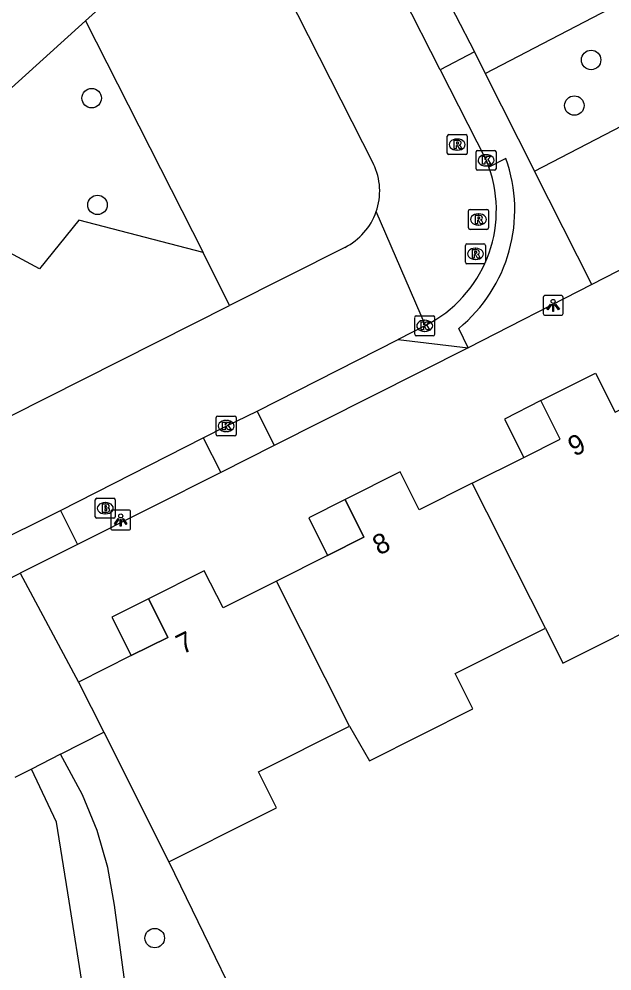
# Model space of a CAD drawing. Extents: x 162722 to 165099, y 384721 to 386283.
# Drawn here: x 163730.52 to 163760.3, y 385039.4 to 385087.19 of the extents above; entities that cross this region are included whole.
import ezdxf

# ---------------------------------------------------------------- set-up
doc = ezdxf.new("R2010")
doc.units = 0
for name, color, linetype in [('IMGEO_Boom', 7, 'Continuous'), ('IMGEO_Brandkraan', 7, 'Continuous'), ('IMGEO_Groenvoorziening', 7, 'Continuous'), ('IMGEO_Kolk', 7, 'Continuous'), ('IMGEO_Lichtpunt', 7, 'Continuous'), ('IMGEO_Pand', 7, 'Continuous'), ('IMGEO_Pand_nummerreeks', 7, 'Continuous'), ('IMGEO_Pand_overbouw', 7, 'Continuous'), ('IMGEO_Parkeervlak_open', 7, 'Continuous'), ('IMGEO_Rijbaan_lokaal_open', 7, 'Continuous'), ('IMGEO_Rioolput', 7, 'Continuous'), ('IMGEO_Voetpad_open', 7, 'Continuous')]:
    doc.layers.add(name, color=color, linetype=linetype)

msp = doc.modelspace()

# ---------------------------------------------------------------- linework, layer by layer
at = {"layer": 'IMGEO_Boom'}
for centre in [(163759.25, 385085.133), (163734.168, 385083.216), (163758.406, 385082.843), (163734.462, 385077.855), (163737.335, 385041.047)]:
    msp.add_circle(centre, 0.489, dxfattribs=at)
at = {"layer": 'IMGEO_Brandkraan'}
for p, q in [((163734.352, 385062.203), (163734.352, 385063.055)), ((163734.427, 385063.129), (163735.279, 385063.129)), ((163735.353, 385063.055), (163735.353, 385062.203)), ((163734.84, 385062.909), (163734.865, 385062.909)), ((163735.279, 385062.129), (163734.427, 385062.129)), ((163734.863, 385062.349), (163734.838, 385062.349))]:
    msp.add_line(p, q, dxfattribs=at)
for points in [[(163734.352, 385062.203), (163734.352, 385063.055)], [(163734.427, 385063.129), (163735.279, 385063.129)], [(163735.353, 385063.055), (163735.353, 385062.203)], [(163734.7, 385062.829), (163734.7, 385062.429), (163734.913, 385062.429)], [(163734.931, 385062.829), (163734.7, 385062.829)], [(163734.879, 385062.748), (163734.825, 385062.748), (163734.825, 385062.672)], [(163734.825, 385062.672), (163734.878, 385062.672)], [(163734.887, 385062.596), (163734.825, 385062.596), (163734.825, 385062.515)], [(163735.279, 385062.129), (163734.427, 385062.129)], [(163734.825, 385062.515), (163734.887, 385062.515)]]:
    msp.add_lwpolyline(points, dxfattribs=at)
for centre, radius, start, end in [((163734.429, 385063.053), 0.0765, 91.552, 178.448), ((163734.429, 385063.053), 0.0765, 91.552, 178.448), ((163735.277, 385063.053), 0.0765, 1.552, 88.448), ((163735.277, 385063.053), 0.0765, 1.552, 88.448), ((163734.88, 385062.71), 0.0379, 267.8285, 90.9355), ((163734.888, 385062.555), 0.0404, 269.8759, 90.5077), ((163734.935, 385062.684), 0.145, 59.4692, 91.5367), ((163734.96, 385062.731), 0.0922, 285.5137, 58.1501), ((163734.965, 385062.539), 0.105, 301.3115, 78.989), ((163734.429, 385062.205), 0.0765, 181.552, 268.448), ((163734.429, 385062.205), 0.0765, 181.552, 268.448), ((163734.919, 385062.68), 0.251, 268.6676, 293.5347), ((163735.277, 385062.205), 0.0765, 271.552, 358.448), ((163735.277, 385062.205), 0.0765, 271.552, 358.448)]:
    msp.add_arc(centre, radius, start, end, dxfattribs=at)
for centre, major_axis, ratio, start_param, end_param in [((163734.839, 385062.629), (-0.387, 0.002), 0.722429, 4.712389, 7.853982), ((163734.864, 385062.629), (-0.39, 0.002), 0.717154, 1.570796, 4.712389)]:
    msp.add_ellipse(centre, major_axis=major_axis, ratio=ratio, start_param=start_param, end_param=end_param, dxfattribs=at)
at = {"layer": 'IMGEO_Groenvoorziening'}
for points in [[(163753.931, 385084.458), (163761.818, 385088.577), (163781.027, 385098.268), (163760.145, 385139.341), (163746.528, 385166.095)], [(163733.852, 385087.089), (163739.773, 385075.459)], [(163739.773, 385075.459), (163733.516, 385077.082), (163731.546, 385074.648), (163729.808, 385075.575), (163728.649, 385075.923), (163727.49, 385076.039), (163727.143, 385076.734), (163727.954, 385078.241), (163728.765, 385080.095), (163728.359, 385082.125)], [(163741.098, 385072.809), (163739.773, 385075.459)], [(163738.045, 385044.879), (163743.285, 385034.094)]]:
    msp.add_lwpolyline(points, dxfattribs=at)
at = {"layer": 'IMGEO_Kolk'}
for p, q in [((163753.473, 385079.668), (163753.473, 385080.52)), ((163753.548, 385080.594), (163754.4, 385080.594)), ((163753.961, 385080.374), (163753.986, 385080.374)), ((163754.474, 385080.52), (163754.474, 385079.668)), ((163753.984, 385079.814), (163753.959, 385079.814)), ((163754.4, 385079.594), (163753.548, 385079.594)), ((163750.392, 385071.359), (163750.392, 385072.211)), ((163750.467, 385072.285), (163751.319, 385072.285)), ((163751.393, 385072.211), (163751.393, 385071.359)), ((163750.88, 385072.065), (163750.905, 385072.065)), ((163751.319, 385071.285), (163750.467, 385071.285)), ((163750.903, 385071.505), (163750.878, 385071.505)), ((163740.422, 385066.329), (163740.422, 385067.181)), ((163740.497, 385067.255), (163741.349, 385067.255)), ((163740.91, 385067.035), (163740.935, 385067.035)), ((163741.423, 385067.181), (163741.423, 385066.329)), ((163740.933, 385066.475), (163740.908, 385066.475)), ((163741.349, 385066.255), (163740.497, 385066.255))]:
    msp.add_line(p, q, dxfattribs=at)
for points in [[(163753.473, 385079.668), (163753.473, 385080.52)], [(163753.548, 385080.594), (163754.4, 385080.594)], [(163753.794, 385080.294), (163753.917, 385080.294), (163753.917, 385080.143), (163754.047, 385080.294), (163754.211, 385080.294), (163754.065, 385080.143), (163754.218, 385079.894), (163754.066, 385079.894), (163753.981, 385080.058), (163753.917, 385079.991), (163753.917, 385079.894), (163753.794, 385079.894), (163753.794, 385080.294)], [(163754.474, 385080.52), (163754.474, 385079.668)], [(163754.4, 385079.594), (163753.548, 385079.594)], [(163750.392, 385071.359), (163750.392, 385072.211)], [(163750.467, 385072.285), (163751.319, 385072.285)], [(163751.393, 385072.211), (163751.393, 385071.359)], [(163750.713, 385071.985), (163750.836, 385071.985), (163750.836, 385071.834), (163750.966, 385071.985), (163751.13, 385071.985), (163750.984, 385071.834), (163751.137, 385071.585), (163750.985, 385071.585), (163750.9, 385071.749), (163750.836, 385071.682), (163750.836, 385071.585), (163750.713, 385071.585), (163750.713, 385071.985)], [(163751.319, 385071.285), (163750.467, 385071.285)], [(163740.422, 385066.329), (163740.422, 385067.181)], [(163740.497, 385067.255), (163741.349, 385067.255)], [(163740.743, 385066.955), (163740.866, 385066.955), (163740.866, 385066.804), (163740.996, 385066.955), (163741.16, 385066.955), (163741.014, 385066.804), (163741.167, 385066.555), (163741.015, 385066.555), (163740.93, 385066.719), (163740.866, 385066.652), (163740.866, 385066.555), (163740.743, 385066.555), (163740.743, 385066.955)], [(163741.423, 385067.181), (163741.423, 385066.329)], [(163741.349, 385066.255), (163740.497, 385066.255)]]:
    msp.add_lwpolyline(points, dxfattribs=at)
for centre, start, end in [((163753.55, 385080.518), 91.552, 178.448), ((163753.55, 385080.518), 91.552, 178.448), ((163754.398, 385080.518), 1.552, 88.448), ((163754.398, 385080.518), 1.552, 88.448), ((163753.55, 385079.67), 181.552, 268.448), ((163753.55, 385079.67), 181.552, 268.448), ((163754.398, 385079.67), 271.552, 358.448), ((163754.398, 385079.67), 271.552, 358.448), ((163750.469, 385072.209), 91.552, 178.448), ((163750.469, 385072.209), 91.552, 178.448), ((163751.317, 385072.209), 1.552, 88.448), ((163751.317, 385072.209), 1.552, 88.448), ((163750.469, 385071.361), 181.552, 268.448), ((163750.469, 385071.361), 181.552, 268.448), ((163751.317, 385071.361), 271.552, 358.448), ((163751.317, 385071.361), 271.552, 358.448), ((163740.499, 385067.179), 91.552, 178.448), ((163740.499, 385067.179), 91.552, 178.448), ((163741.347, 385067.179), 1.552, 88.448), ((163741.347, 385067.179), 1.552, 88.448), ((163740.499, 385066.331), 181.552, 268.448), ((163740.499, 385066.331), 181.552, 268.448), ((163741.347, 385066.331), 271.552, 358.448), ((163741.347, 385066.331), 271.552, 358.448)]:
    msp.add_arc(centre, 0.0765, start, end, dxfattribs=at)
for centre, major_axis, ratio, start_param, end_param in [((163753.96, 385080.094), (-0.387, 0.002), 0.722429, 4.712389, 7.853982), ((163753.985, 385080.094), (-0.39, 0.002), 0.717154, 1.570796, 4.712389), ((163750.879, 385071.785), (-0.387, 0.002), 0.722429, 4.712389, 7.853982), ((163750.904, 385071.785), (-0.39, 0.002), 0.717154, 1.570796, 4.712389), ((163740.909, 385066.755), (-0.387, 0.002), 0.722429, 4.712389, 7.853982), ((163740.934, 385066.755), (-0.39, 0.002), 0.717154, 1.570796, 4.712389)]:
    msp.add_ellipse(centre, major_axis=major_axis, ratio=ratio, start_param=start_param, end_param=end_param, dxfattribs=at)
at = {"layer": 'IMGEO_Lichtpunt'}
for p, q in [((163756.844, 385073.214), (163756.844, 385072.407)), ((163756.844, 385073.214), (163756.844, 385072.407)), ((163757.746, 385073.309), (163756.938, 385073.309)), ((163757.746, 385073.309), (163756.938, 385073.309)), ((163757.84, 385072.407), (163757.84, 385073.214)), ((163757.84, 385072.407), (163757.84, 385073.214)), ((163756.938, 385072.313), (163757.746, 385072.313)), ((163756.938, 385072.313), (163757.746, 385072.313)), ((163735.127, 385062.441), (163735.127, 385061.634)), ((163735.127, 385062.441), (163735.127, 385061.634)), ((163736.029, 385062.536), (163735.221, 385062.536)), ((163736.029, 385062.536), (163735.221, 385062.536)), ((163736.123, 385061.634), (163736.123, 385062.441)), ((163736.123, 385061.634), (163736.123, 385062.441)), ((163735.221, 385061.54), (163736.029, 385061.54)), ((163735.221, 385061.54), (163736.029, 385061.54))]:
    msp.add_line(p, q, dxfattribs=at)
for points in [[(163757.218, 385072.878), (163757.257, 385072.85), (163757.069, 385072.588), (163757.031, 385072.615), (163757.218, 385072.878)], [(163757.32, 385072.83), (163757.367, 385072.83), (163757.367, 385072.508), (163757.32, 385072.508), (163757.32, 385072.83)], [(163757.43, 385072.85), (163757.468, 385072.877), (163757.655, 385072.615), (163757.616, 385072.587), (163757.43, 385072.85)], [(163735.501, 385062.105), (163735.54, 385062.077), (163735.352, 385061.815), (163735.314, 385061.842), (163735.501, 385062.105)], [(163735.713, 385062.077), (163735.751, 385062.104), (163735.938, 385061.842), (163735.899, 385061.814), (163735.713, 385062.077)], [(163735.603, 385062.057), (163735.65, 385062.057), (163735.65, 385061.735), (163735.603, 385061.735), (163735.603, 385062.057)]]:
    msp.add_lwpolyline(points, dxfattribs=at)
for centre in [(163757.343, 385073.012), (163735.626, 385062.239)]:
    msp.add_circle(centre, 0.0994, dxfattribs=at)
for centre, start, end in [((163756.938, 385073.214), 90, 180), ((163756.938, 385073.214), 90, 180), ((163757.746, 385073.214), 0, 90), ((163757.746, 385073.214), 0, 90), ((163756.938, 385072.407), 180, 270), ((163756.938, 385072.407), 180, 270), ((163757.746, 385072.407), 270, 0), ((163757.746, 385072.407), 270, 360), ((163735.221, 385062.441), 90, 180), ((163735.221, 385062.441), 90, 180), ((163736.029, 385062.441), 0, 90), ((163736.029, 385062.441), 0, 90), ((163735.221, 385061.634), 180, 270), ((163735.221, 385061.634), 180, 270), ((163736.029, 385061.634), 270, 0), ((163736.029, 385061.634), 270, 360)]:
    msp.add_arc(centre, 0.0946, start, end, dxfattribs=at)
at = {"layer": 'IMGEO_Pand'}
for points in [[(163753.284, 385063.881), (163755.865, 385065.177), (163757.701, 385066.099), (163756.732, 385068.029), (163759.469, 385069.404), (163760.451, 385067.447), (163763.416, 385068.936)], [(163753.284, 385063.881), (163750.622, 385062.544), (163749.666, 385064.449), (163746.895, 385063.058), (163747.84, 385061.177), (163746.017, 385060.261), (163743.454, 385058.974)], [(163756.951, 385056.602), (163753.284, 385063.881)], [(163756.951, 385056.602), (163757.832, 385054.849), (163758.028, 385054.947), (163762.769, 385057.329), (163763.622, 385055.631), (163768.76, 385058.212), (163767.9, 385060.037)], [(163743.454, 385058.974), (163740.765, 385057.623), (163739.826, 385059.492), (163737.023, 385058.085), (163737.035, 385058.063), (163737.998, 385056.138), (163736.157, 385055.226), (163733.515, 385053.899)], [(163747.123, 385051.691), (163743.454, 385058.974)], [(163747.123, 385051.691), (163748.113, 385049.942), (163753.315, 385052.554), (163752.423, 385054.328), (163756.951, 385056.602)], [(163733.515, 385053.899), (163734.778, 385051.385)], [(163738.045, 385044.879), (163742.514, 385047.123), (163743.452, 385047.594), (163742.548, 385049.393), (163747.123, 385051.691)], [(163734.778, 385051.385), (163738.045, 385044.879)]]:
    msp.add_lwpolyline(points, dxfattribs=at)
at = {"layer": 'IMGEO_Pand_overbouw'}
for points in [[(163756.732, 385068.029), (163754.896, 385067.107), (163755.865, 385065.177), (163757.701, 385066.099)], [(163746.895, 385063.058), (163745.072, 385062.142), (163746.017, 385060.261), (163747.84, 385061.177)], [(163737.023, 385058.085), (163735.185, 385057.162), (163736.157, 385055.226), (163737.998, 385056.138)]]:
    msp.add_lwpolyline(points, close=True, dxfattribs=at)
at = {"layer": 'IMGEO_Parkeervlak_open'}
for points in [[(163730.584, 385059.363), (163733.515, 385053.899)], [(163732.602, 385050.277), (163734.778, 385051.385)], [(163731.143, 385049.533), (163730.314, 385049.111)]]:
    msp.add_lwpolyline(points, dxfattribs=at)
at = {"layer": 'IMGEO_Rijbaan_lokaal_open'}
for points in [[(163733.852, 385087.089), (163738.829, 385091.585)], [(163742.868, 385090.668), (163748.325, 385079.906)], [(163751.676, 385084.642), (163749.785, 385088.372)], [(163728.359, 385082.125), (163733.852, 385087.089)], [(163751.676, 385084.642), (163753.974, 385080.094), (163754.119, 385079.757)], [(163756.413, 385079.553), (163766.533, 385084.8)], [(163759.29, 385073.861), (163756.413, 385079.553)], [(163769.461, 385079.078), (163759.29, 385073.861)], [(163750.929, 385071.803), (163748.458, 385077.517)], [(163746.876, 385075.723), (163741.098, 385072.809)], [(163730.104, 385067.264), (163741.098, 385072.809)], [(163750.929, 385071.803), (163749.555, 385071.092)], [(163742.473, 385067.507), (163749.555, 385071.092)], [(163739.772, 385066.169), (163740.923, 385066.755), (163742.473, 385067.507)], [(163732.601, 385062.516), (163739.772, 385066.169)], [(163725.262, 385058.861), (163732.601, 385062.516)]]:
    msp.add_lwpolyline(points, dxfattribs=at)
for centre, radius, start, end in [((163745.48, 385078.549), 3.152, 340.8784, 25.4945), ((163748.006, 385077.592), 6.485, 296.7913, 19.5016), ((163745.482, 385078.547), 3.149, 296.2734, 340.913)]:
    msp.add_arc(centre, radius, start, end, dxfattribs=at)
at = {"layer": 'IMGEO_Rioolput'}
for p, q in [((163752.027, 385080.457), (163752.027, 385081.309)), ((163752.102, 385081.383), (163752.954, 385081.383)), ((163753.028, 385081.309), (163753.028, 385080.457)), ((163752.515, 385081.163), (163752.54, 385081.163)), ((163752.954, 385080.383), (163752.102, 385080.383)), ((163752.538, 385080.603), (163752.513, 385080.603)), ((163753.093, 385076.699), (163753.093, 385077.551)), ((163753.168, 385077.625), (163754.02, 385077.625)), ((163753.581, 385077.405), (163753.606, 385077.405)), ((163754.094, 385077.551), (163754.094, 385076.699)), ((163754.02, 385076.625), (163753.168, 385076.625)), ((163753.604, 385076.845), (163753.579, 385076.845)), ((163752.941, 385074.973), (163752.941, 385075.825)), ((163753.016, 385075.899), (163753.868, 385075.899)), ((163753.429, 385075.679), (163753.454, 385075.679)), ((163753.942, 385075.825), (163753.942, 385074.973)), ((163753.452, 385075.119), (163753.427, 385075.119)), ((163753.868, 385074.899), (163753.016, 385074.899))]:
    msp.add_line(p, q, dxfattribs=at)
for points in [[(163752.027, 385080.457), (163752.027, 385081.309)], [(163752.102, 385081.383), (163752.954, 385081.383)], [(163753.028, 385081.309), (163753.028, 385080.457)], [(163752.616, 385081.081), (163752.364, 385081.083), (163752.364, 385080.683)], [(163752.364, 385080.683), (163752.488, 385080.683), (163752.488, 385080.845), (163752.499, 385080.845)], [(163752.542, 385081.002), (163752.488, 385081.002), (163752.488, 385080.921)], [(163752.488, 385080.921), (163752.54, 385080.921)], [(163752.546, 385080.816), (163752.617, 385080.683), (163752.757, 385080.683), (163752.692, 385080.809)], [(163752.954, 385080.383), (163752.102, 385080.383)], [(163753.093, 385076.699), (163753.093, 385077.551)], [(163753.168, 385077.625), (163754.02, 385077.625)], [(163754.094, 385077.551), (163754.094, 385076.699)], [(163753.682, 385077.323), (163753.43, 385077.325), (163753.43, 385076.925)], [(163753.43, 385076.925), (163753.554, 385076.925), (163753.554, 385077.087), (163753.565, 385077.087)], [(163753.608, 385077.244), (163753.554, 385077.244), (163753.554, 385077.163)], [(163753.554, 385077.163), (163753.606, 385077.163)], [(163753.612, 385077.058), (163753.683, 385076.925), (163753.823, 385076.925), (163753.758, 385077.051)], [(163754.02, 385076.625), (163753.168, 385076.625)], [(163752.941, 385074.973), (163752.941, 385075.825)], [(163753.016, 385075.899), (163753.868, 385075.899)], [(163753.53, 385075.597), (163753.278, 385075.599), (163753.278, 385075.199)], [(163753.456, 385075.518), (163753.402, 385075.518), (163753.402, 385075.437)], [(163753.942, 385075.825), (163753.942, 385074.973)], [(163753.278, 385075.199), (163753.402, 385075.199), (163753.402, 385075.361), (163753.413, 385075.361)], [(163753.402, 385075.437), (163753.454, 385075.437)], [(163753.46, 385075.332), (163753.531, 385075.199), (163753.671, 385075.199), (163753.606, 385075.325)], [(163753.868, 385074.899), (163753.016, 385074.899)]]:
    msp.add_lwpolyline(points, dxfattribs=at)
for centre, radius, start, end in [((163752.104, 385081.307), 0.0765, 91.552, 178.448), ((163752.104, 385081.307), 0.0765, 91.552, 178.448), ((163752.952, 385081.307), 0.0765, 1.552, 88.448), ((163752.952, 385081.307), 0.0765, 1.552, 88.448), ((163752.498, 385080.792), 0.0533, 26.0293, 88.6989), ((163752.524, 385081.11), 0.19, 274.7715, 282.9687), ((163752.548, 385080.906), 0.0964, 77.0061, 93.1865), ((163752.562, 385080.963), 0.0378, 276.6634, 79.6772), ((163752.615, 385080.971), 0.109, 350.3612, 89.416), ((163752.613, 385080.971), 0.112, 277.5842, 350.9817), ((163752.597, 385080.756), 0.108, 29.5134, 73.7905), ((163752.104, 385080.459), 0.0765, 181.552, 268.448), ((163752.104, 385080.459), 0.0765, 181.552, 268.448), ((163752.952, 385080.459), 0.0765, 271.552, 358.448), ((163752.952, 385080.459), 0.0765, 271.552, 358.448), ((163753.17, 385077.549), 0.0765, 91.552, 178.448), ((163753.17, 385077.549), 0.0765, 91.552, 178.448), ((163754.018, 385077.549), 0.0765, 1.552, 88.448), ((163754.018, 385077.549), 0.0765, 1.552, 88.448), ((163753.564, 385077.034), 0.0533, 26.0293, 88.6989), ((163753.59, 385077.352), 0.19, 274.7715, 282.9687), ((163753.614, 385077.148), 0.0964, 77.0061, 93.1865), ((163753.628, 385077.205), 0.0378, 276.6634, 79.6772), ((163753.681, 385077.213), 0.109, 350.3612, 89.416), ((163753.679, 385077.213), 0.112, 277.5842, 350.9817), ((163753.663, 385076.998), 0.108, 29.5134, 73.7905), ((163753.17, 385076.701), 0.0765, 181.552, 268.448), ((163753.17, 385076.701), 0.0765, 181.552, 268.448), ((163754.018, 385076.701), 0.0765, 271.552, 358.448), ((163754.018, 385076.701), 0.0765, 271.552, 358.448), ((163753.018, 385075.823), 0.0765, 91.552, 178.448), ((163753.018, 385075.823), 0.0765, 91.552, 178.448), ((163753.462, 385075.422), 0.0964, 77.0061, 93.1865), ((163753.476, 385075.479), 0.0378, 276.6634, 79.6772), ((163753.529, 385075.487), 0.109, 350.3612, 89.416), ((163753.527, 385075.487), 0.112, 277.5842, 350.9817), ((163753.866, 385075.823), 0.0765, 1.552, 88.448), ((163753.866, 385075.823), 0.0765, 1.552, 88.448), ((163753.412, 385075.308), 0.0533, 26.0293, 88.6989), ((163753.438, 385075.626), 0.19, 274.7715, 282.9687), ((163753.511, 385075.272), 0.108, 29.5134, 73.7905), ((163753.018, 385074.975), 0.0765, 181.552, 268.448), ((163753.018, 385074.975), 0.0765, 181.552, 268.448), ((163753.866, 385074.975), 0.0765, 271.552, 358.448), ((163753.866, 385074.975), 0.0765, 271.552, 358.448)]:
    msp.add_arc(centre, radius, start, end, dxfattribs=at)
for centre, major_axis, ratio, start_param, end_param in [((163752.514, 385080.883), (-0.387, 0.002), 0.722429, 4.712389, 7.853982), ((163752.539, 385080.883), (-0.39, 0.002), 0.717154, 1.570796, 4.712389), ((163753.58, 385077.125), (-0.387, 0.002), 0.722429, 4.712389, 7.853982), ((163753.605, 385077.125), (-0.39, 0.002), 0.717154, 1.570796, 4.712389), ((163753.428, 385075.399), (-0.387, 0.002), 0.722429, 4.712389, 7.853982), ((163753.453, 385075.399), (-0.39, 0.002), 0.717154, 1.570796, 4.712389)]:
    msp.add_ellipse(centre, major_axis=major_axis, ratio=ratio, start_param=start_param, end_param=end_param, dxfattribs=at)
at = {"layer": 'IMGEO_Voetpad_open'}
for points in [[(163751.491, 385089.235), (163753.386, 385085.536)], [(163753.386, 385085.536), (163751.676, 385084.642)], [(163753.386, 385085.536), (163753.931, 385084.458)], [(163753.931, 385084.458), (163756.413, 385079.553)], [(163754.972, 385080.192), (163754.119, 385079.757)], [(163759.29, 385073.861), (163753.075, 385070.688)], [(163753.075, 385070.688), (163752.602, 385071.647)], [(163753.075, 385070.688), (163743.33, 385065.783)], [(163749.555, 385071.092), (163753.075, 385070.688)], [(163742.473, 385067.507), (163743.33, 385065.783)], [(163739.772, 385066.169), (163740.658, 385064.429)], [(163743.33, 385065.783), (163740.658, 385064.429)], [(163740.658, 385064.429), (163733.463, 385060.799)], [(163732.601, 385062.516), (163733.463, 385060.799)], [(163733.463, 385060.799), (163730.584, 385059.363)], [(163726.172, 385057.128), (163730.584, 385059.363)], [(163732.602, 385050.277), (163731.143, 385049.533)], [(163736.866, 385031.109), (163735.313, 385042.695), (163734.975, 385044.596), (163734.441, 385046.451), (163733.716, 385048.241), (163732.602, 385050.277)], [(163733.752, 385038.348), (163733.034, 385042.907), (163732.409, 385046.872), (163731.143, 385049.533)]]:
    msp.add_lwpolyline(points, dxfattribs=at)
msp.add_arc((163747.701, 385077.607), 7.716, 309.4275, 19.5692, dxfattribs=at)

# ---------------------------------------------------------------- texts
at = {"layer": 'IMGEO_Pand_nummerreeks'}
for s, rotation, p in [('9', 26.6712, (163758.409, 385065.201)), ('8', 26.6655, (163748.599, 385060.243)), ('7', 26.6597, (163738.731, 385055.272))]:
    msp.add_text(s, height=1, rotation=rotation, dxfattribs=at).set_placement(p)

doc.saveas('drawing.dxf')
